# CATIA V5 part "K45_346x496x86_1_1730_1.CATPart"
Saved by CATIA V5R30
Part number: ROZPERNA DESKA
Bounding box of the stored display mesh (mm): x 0 to 86, y -248 to 248, z -173 to 173
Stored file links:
  C:\Users\ondra\Desktop\PŘÍLOHA P III\CATIA\K45_346x496x86_1_1730_1.CATPart
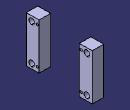
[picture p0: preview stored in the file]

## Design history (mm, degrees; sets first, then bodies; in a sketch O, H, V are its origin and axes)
Set1
  DatumSurface1 to DatumSurface28 "K45/346x"
  Plane1: type Offset, RefPlane yz-plane, Offset 86
  Join1: Elements (DatumSurface1; DatumSurface2; DatumSurface3; DatumSurface4; DatumSurface5; DatumSurface6; DatumSurface7; DatumSurface8; DatumSurface9; DatumSurface10; DatumSurface11; DatumSurface12; DatumSurface13; DatumSurface14; DatumSurface15; DatumSurface16; DatumSurface17; DatumSurface18; DatumSurface19; DatumSurface20; DatumSurface21; DatumSurface22; DatumSurface23; DatumSurface24; DatumSurface25; DatumSurface26; DatumSurface27; DatumSurface28)
Body1 (main body)
  CloseSurface1: CloseElement Join1
  DatumCurve1
  DatumCurve2
  Sketch1 on zx-plane, origin (0, 0, 0), H (-1, 0, 0), V (0, 0, 1)
    reference projected arc E1 centre (-43, 80) radius 12.5 from (-55.5, 80) to (-30.5, 80) ccw from edge of DatumCurve1
    reference projected arc E2 centre (-43, -80) radius 12.5 from (-55.5, -80) to (-30.5, -80) ccw from edge of DatumCurve2
    point P5 (-43, -80)
    point P6 (-43, 80)
    concentricity: P5 E2, P6 E1
  Sketch2 on {plane type Tangent, Support face of CloseSurface1, RefPoint Sketch1.P5}, origin (43, 0, -80), H (1, 0, 0), V (0, 0, -1)
    point P1 (0, 0)
    reference projected point E1 (0, 0) from Sketch1.P5
    coincidence: E1 P1
  Hole1: placed by Sketch2, at (43, -248, -80) direction (0, 1, 0), diameter 8.376, depth 20, V-bottom angle 120, threaded "M10", thread diameter 10, thread depth 17, pitch 1.5
  UserPattern1: of Hole1, copies 2, at the points of Sketch1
